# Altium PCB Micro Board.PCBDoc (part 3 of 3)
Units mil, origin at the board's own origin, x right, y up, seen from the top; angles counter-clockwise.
Board outline 8525 x 5525 mil, 2 copper layers (Top Layer, Bottom Layer); 82 components, 533 nets, 1257 pads, 165 vias.
Unrouted connection lines stored in the file: 4.
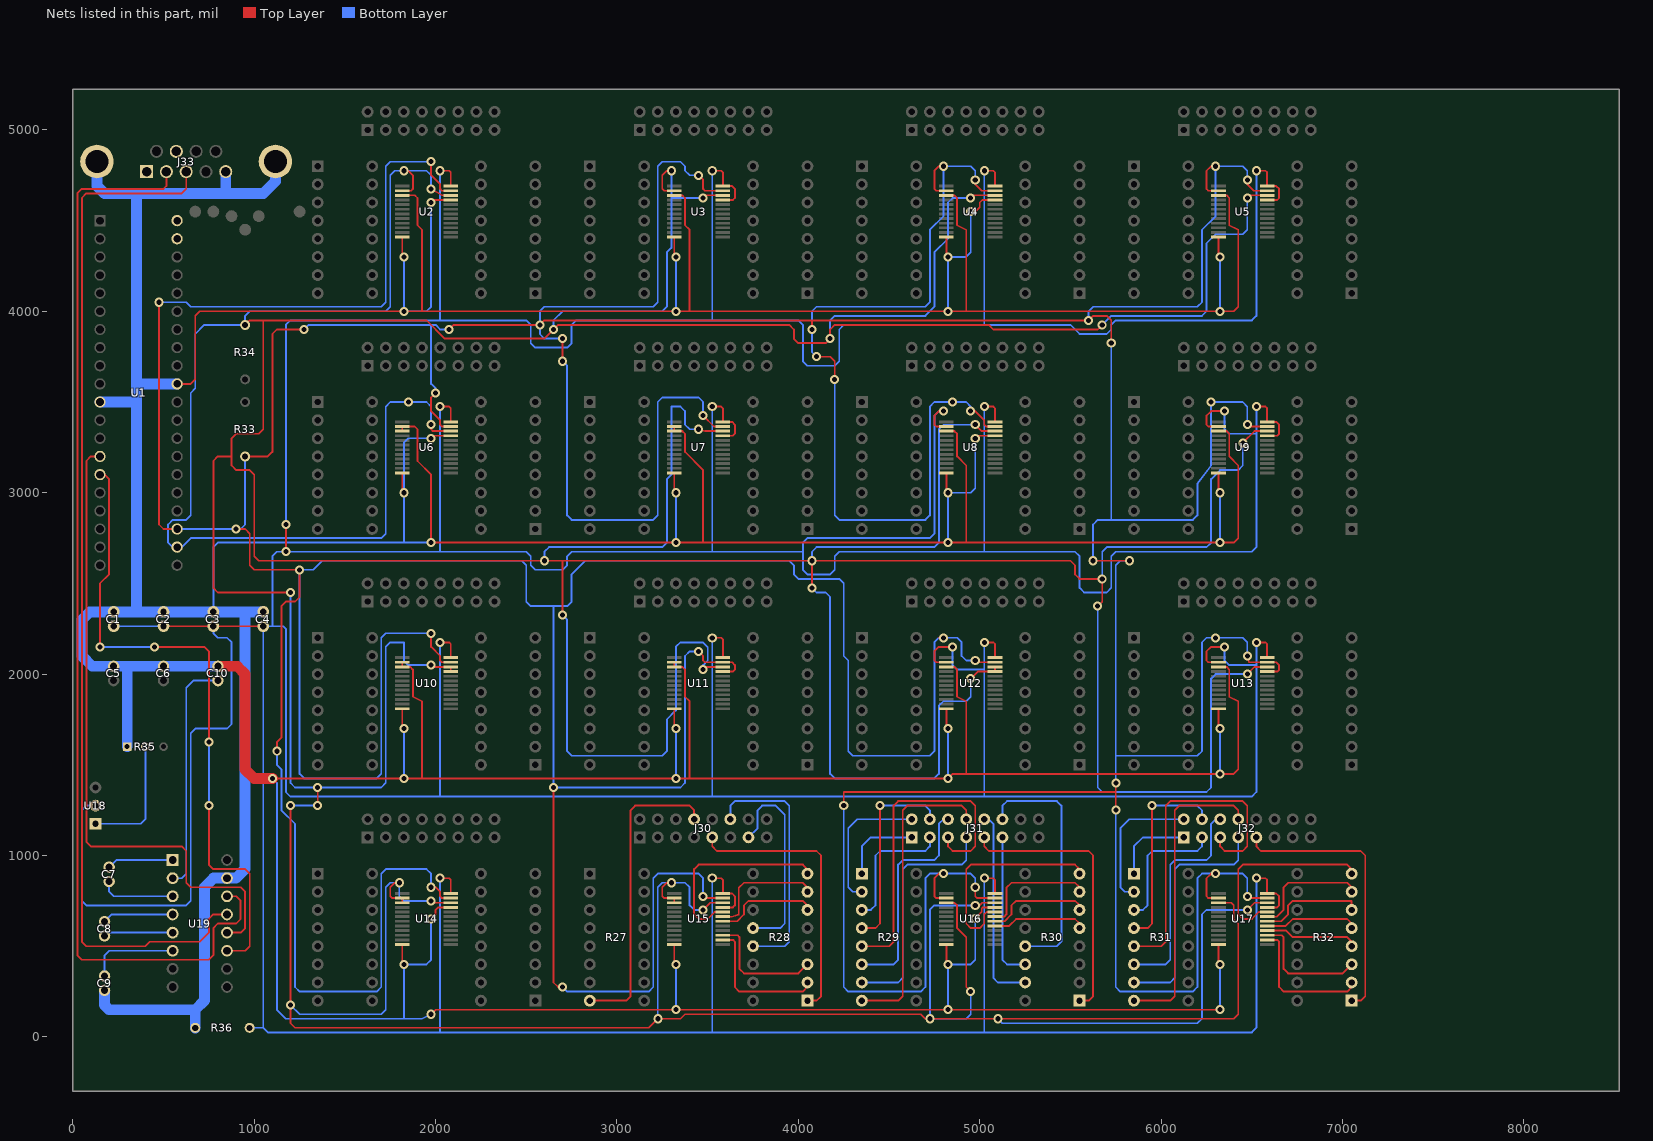
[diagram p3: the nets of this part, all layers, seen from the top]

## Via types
v1: diameter 50, hole 28, Top Layer to Bottom Layer, 165 vias

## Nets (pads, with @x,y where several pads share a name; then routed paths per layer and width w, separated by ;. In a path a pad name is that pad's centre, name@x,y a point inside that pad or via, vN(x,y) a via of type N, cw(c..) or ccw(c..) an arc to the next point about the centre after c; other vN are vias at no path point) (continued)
B216: J30.8 R27.8 | length 1681.1
  Top Layer w10: R27.8@2850,200 3050,200 3075,225 3075,1250 3100,1275 3400,1275 3425,1250 J30.8@3425,1200
B217: R28.16 U15.13 | length 465.9
  Top Layer w10: U15.13@3583.86,509.25 3583.86,216.14 3600,200 R28.16@3750,200
B217: J30.9 R28.1 | length 1531.1
  Top Layer w10: J30.9@3525,1100 3525,1050 3550,1025 4100,1025 4125,1000 4125,225 4100,200 R28.1@4050,200
B218: J30.10 R28.15 | length 1095.7
  Bottom Layer w10: J30.10@3525,1200 3550,1200 3575,1175 3575,325 3600,300 R28.15@3750,300
B218: R28.2 U15.14 | length 765.9
  Top Layer w10: U15.14@3583.86,534.84 3640.16,534.84 3650,525 3650,275 3675,250 4025,250 4050,275 R28.2@4050,300
B219: J30.11 R28.14 | length 810.4
  Bottom Layer w10: J30.11@3625,1100 3625,425 3650,400 R28.14@3750,400
B219: R28.3 U15.15 | length 676.5
  Top Layer w10: U15.15@3583.86,560.43 3664.57,560.43 3675,550 3675,375 3700,350 4000,350 R28.3@4050,400
B220: R28.4 U15.16 | length 516.4
  Top Layer w10: U15.16@3583.86,586.02 3688.98,586.02 3725,550 4025,550 4050,525 R28.4@4050,500
B220: J30.12 R28.13 | length 1381.1
  Bottom Layer w10: J30.12@3625,1200 3625,1275 3650,1300 3925,1300 3950,1275 3950,525 3925,500 R28.13@3750,500
B221: R28.5 U15.17 | length 517.4
  Top Layer w10: U15.17@3583.86,611.61 3686.61,611.61 3725,650 4025,650 4050,625 R28.5@4050,600
B221: J30.13 R28.12 | length 1137.1
  Bottom Layer w10: J30.13@3725,1100 3775,1150 3775,1250 3800,1275 3875,1275 3925,1225 3925,625 3900,600 R28.12@3750,600
B222: J30.14 R28.11 | length 581.1
  Bottom Layer w10: J30.14@3725,1200 3675,1150 3675,725 3700,700 R28.11@3750,700
B222: R28.6 U15.18 | length 577.5
  Top Layer w10: U15.18@3583.86,637.2 3662.2,637.2 3700,675 3700,725 3725,750 4025,750 4050,725 R28.6@4050,700
B223: J30.15 R28.10 | length 431.1
  Bottom Layer w10: R28.10@3750,800 3725,800 3700,825 3700,950 3725,975 3800,975 3825,1000 J30.15@3825,1100
B223: R28.7 U15.19 | length 661.9
  Top Layer w10: U15.19@3583.86,662.8 3634.51,662.8 3671.72,675 3671.72,821.72 3700,850 4025,850 4050,825 R28.7@4050,800
B224: J30.16 R28.9 | length 495.7
  Bottom Layer w10: R28.9@3750,900 3875,900 3900,925 3900,1175 3875,1200 J30.16@3825,1200
B224: R28.8 U15.20 | length 1105.8
  Top Layer w10: U15.20@3583.86,688.39 3538.39,688.39 3500,650 3450,650 3425,675 3425,925 3450,950 4025,950 4050,925 R28.8@4050,900
B225: R29.16 U16.4 | length 331.1
  Top Layer w10: R29.16@4650,900 4700,900 4725,875 4725,725 4736.02,713.98 U16.4@4816.14,713.98
B225: J31.1 R29.1 | length 445.7
  Bottom Layer w10: R29.1@4350,900 4350,1050 4400,1100 J31.1@4625,1100
B226: R29.15 U16.5 | length 256.3
  Top Layer w10: R29.15@4650,800 4675,800 4700,775 4700,700 4711.61,688.39 U16.5@4816.14,688.39
B226: J31.2 R29.2 | length 781.1
  Bottom Layer w10: R29.2@4350,800 4300,800 4275,825 4275,1150 4325,1200 J31.2@4625,1200
B227: R29.14 U16.6 | length 181.6
  Top Layer w10: R29.14@4650,700 4687.2,662.8 U16.6@4816.14,662.8
B227: J31.3 R29.3 | length 731.1
  Bottom Layer w10: R29.3@4350,700 4400,700 4425,725 4425,1000 4450,1025 4700,1025 4725,1050 J31.3@4725,1100
B228: R29.13 U16.7 | length 146.2
  Top Layer w10: 4675,625 4687.2,637.2 U16.7@4816.14,637.2
B228: J31.4 R29.4 | length 1095.7
  Top Layer w10: R29.4@4350,600 4425,600 4450,625 v1(4450,1275)
  Bottom Layer w10: v1(4450,1275) 4700,1275 4725,1250 J31.4@4725,1200
B229: R29.12 U16.8 | length 256.3
  Top Layer w10: R29.12@4650,500 4675,500 4700,525 4700,600 4711.61,611.61 U16.8@4816.14,611.61
B229: J31.5 R29.5 | length 1851.8
  Top Layer w10: R29.5@4350,500 4500,500 4525,525 4525,1275 4550,1300 4950,1300 4975,1275 4975,1050 4950,1025 4850,1025 4825,1050 J31.5@4825,1100
B230: R29.11 U16.9 | length 331.1
  Top Layer w10: R29.11@4650,400 4700,400 4725,425 4725,575 4736.02,586.02 U16.9@4816.14,586.02
B230: J31.6 R29.6 | length 1216.4
  Bottom Layer w10: R29.6@4350,400 4525,400 4550,425 4550,950 4575,975 4750,975 4775,1000 4775,1175 4800,1200 J31.6@4825,1200
B231: R29.10 U16.10 | length 405.8
  Top Layer w10: R29.10@4650,300 4725,300 4750,325 4750,550 4760.43,560.43 U16.10@4816.14,560.43
B231: J31.7 R29.7 | length 1331.1
  Bottom Layer w10: R29.7@4350,300 4550,300 4575,325 4575,925 4600,950 4900,950 4925,975 J31.7@4925,1100
B232: R29.9 U16.11 | length 648.3
  Top Layer w10: R29.9@4650,200 4875,200 4900,225 4900,525 4890.16,534.84 U16.11@4816.14,534.84
B232: J31.8 R29.8 | length 1681.1
  Top Layer w10: R29.8@4350,200 4550,200 4575,225 4575,1250 4600,1275 4900,1275 4925,1250 J31.8@4925,1200
B233: R30.16 U16.13 | length 465.9
  Top Layer w10: U16.13@5083.86,509.25 5083.86,216.14 5100,200 R30.16@5250,200
B233: J31.9 R30.1 | length 1531.1
  Top Layer w10: J31.9@5025,1100 5025,1050 5050,1025 5600,1025 5625,1000 5625,225 5600,200 R30.1@5550,200
B234: R30.2 U16.14 | length 765.9
  Top Layer w10: U16.14@5083.86,534.84 5140.16,534.84 5150,525 5150,275 5175,250 5525,250 5550,275 R30.2@5550,300
B234: J31.10 R30.15 | length 1095.7
  Bottom Layer w10: J31.10@5025,1200 5050,1200 5075,1175 5075,325 5100,300 R30.15@5250,300
B235: R30.3 U16.15 | length 676.5
  Top Layer w10: U16.15@5083.86,560.43 5164.57,560.43 5175,550 5175,375 5200,350 5500,350 R30.3@5550,400
B235: J31.11 R30.14 | length 810.4
  Bottom Layer w10: J31.11@5125,1100 5125,425 5150,400 R30.14@5250,400
B236: R30.4 U16.16 | length 516.4
  Top Layer w10: U16.16@5083.86,586.02 5188.98,586.02 5225,550 5525,550 5550,525 R30.4@5550,500
B236: J31.12 R30.13 | length 1381.1
  Bottom Layer w10: J31.12@5125,1200 5125,1275 5150,1300 5425,1300 5450,1275 5450,525 5425,500 R30.13@5250,500
B237: J31.13 R30.12 | length 1137.1
  Bottom Layer w10: J31.13@5225,1100 5275,1150 5275,1250 5300,1275 5375,1275 5425,1225 5425,625 5400,600 R30.12@5250,600
B237: R30.5 U16.17 | length 517.4
  Top Layer w10: U16.17@5083.86,611.61 5161.61,611.61 5200,650 5525,650 5550,625 R30.5@5550,600
B238: J31.14 R30.11 | length 581.1
  Bottom Layer w10: J31.14@5225,1200 5175,1150 5175,725 5200,700 R30.11@5250,700
B238: R30.6 U16.18 | length 577.5
  Top Layer w10: U16.18@5083.86,637.2 5137.2,637.2 5175,675 5175,725 5200,750 5525,750 5550,725 R30.6@5550,700
B239: J31.15 R30.10 | length 431.1
  Bottom Layer w10: R30.10@5250,800 5225,800 5200,825 5200,950 5225,975 5300,975 5325,1000 J31.15@5325,1100
B239: R30.7 U16.19 | length 665
  Top Layer w10: U16.19@5083.86,662.8 5134.51,662.8 5146.72,675 5146.72,821.72 5175,850 5525,850 5550,825 R30.7@5550,800
B240: J31.16 R30.9 | length 495.7
  Bottom Layer w10: R30.9@5250,900 5375,900 5400,925 5400,1175 5375,1200 J31.16@5325,1200
B240: R30.8 U16.20 | length 1205.8
  Top Layer w10: U16.20@5083.86,688.39 5038.39,688.39 5025,675 5025,625 5000,600 4950,600 4925,625 4925,925 4950,950 5525,950 5550,925 R30.8@5550,900
B241: R31.16 U17.4 | length 331.1
  Top Layer w10: R31.16@6150,900 6200,900 6225,875 6225,725 6236.02,713.98 U17.4@6316.14,713.98
B241: J32.1 R31.1 | length 445.7
  Bottom Layer w10: R31.1@5850,900 5850,1050 5900,1100 J32.1@6125,1100
B242: R31.15 U17.5 | length 256.3
  Top Layer w10: R31.15@6150,800 6175,800 6200,775 6200,700 6211.61,688.39 U17.5@6316.14,688.39
B242: J32.2 R31.2 | length 781.1
  Bottom Layer w10: R31.2@5850,800 5800,800 5775,825 5775,1150 5825,1200 J32.2@6125,1200
B243: R31.14 U17.6 | length 181.6
  Top Layer w10: R31.14@6150,700 6187.2,662.8 U17.6@6316.14,662.8
B243: J32.3 R31.3 | length 731.1
  Bottom Layer w10: R31.3@5850,700 5900,700 5925,725 5925,1000 5950,1025 6200,1025 6225,1050 J32.3@6225,1100
B244: R31.13 U17.7 | length 146.2
  Top Layer w10: 6175,625 6187.2,637.2 U17.7@6316.14,637.2
B244: J32.4 R31.4 | length 1095.7
  Top Layer w10: R31.4@5850,600 5925,600 5950,625 v1(5950,1275)
  Bottom Layer w10: v1(5950,1275) 6200,1275 6225,1250 J32.4@6225,1200
B245: R31.12 U17.8 | length 256.3
  Top Layer w10: R31.12@6150,500 6175,500 6200,525 6200,600 6211.61,611.61 U17.8@6316.14,611.61
B245: J32.5 R31.5 | length 1851.8
  Top Layer w10: R31.5@5850,500 6000,500 6025,525 6025,1275 6050,1300 6450,1300 6475,1275 6475,1050 6450,1025 6350,1025 6325,1050 J32.5@6325,1100
B246: R31.11 U17.9 | length 331.1
  Top Layer w10: R31.11@6150,400 6200,400 6225,425 6225,575 6236.02,586.02 U17.9@6316.14,586.02
B246: J32.6 R31.6 | length 1216.4
  Bottom Layer w10: R31.6@5850,400 6025,400 6050,425 6050,950 6075,975 6250,975 6275,1000 6275,1175 6300,1200 J32.6@6325,1200
B247: R31.10 U17.10 | length 405.8
  Top Layer w10: R31.10@6150,300 6225,300 6250,325 6250,550 6260.43,560.43 U17.10@6316.14,560.43
B247: J32.7 R31.7 | length 1331.1
  Bottom Layer w10: R31.7@5850,300 6050,300 6075,325 6075,925 6100,950 6400,950 6425,975 J32.7@6425,1100
B248: R31.9 U17.11 | length 648.3
  Top Layer w10: R31.9@6150,200 6375,200 6400,225 6400,525 6390.16,534.84 U17.11@6316.14,534.84
B248: J32.8 R31.8 | length 1681.1
  Top Layer w10: R31.8@5850,200 6050,200 6075,225 6075,1250 6100,1275 6400,1275 6425,1250 J32.8@6425,1200
B249: R32.16 U17.13 | length 465.9
  Top Layer w10: U17.13@6583.86,509.25 6583.86,216.14 6600,200 R32.16@6750,200
B249: J32.9 R32.1 | length 1531.1
  Top Layer w10: J32.9@6525,1100 6525,1050 6550,1025 7100,1025 7125,1000 7125,225 7100,200 R32.1@7050,200
B250: J32.10 R32.15 | length 1095.7
  Bottom Layer w10: J32.10@6525,1200 6550,1200 6575,1175 6575,325 6600,300 R32.15@6750,300
B250: R32.2 U17.14 | length 765.9
  Top Layer w10: U17.14@6583.86,534.84 6640.16,534.84 6650,525 6650,275 6675,250 7025,250 7050,275 R32.2@7050,300
B251: J32.11 R32.14 | length 810.4
  Bottom Layer w10: J32.11@6625,1100 6625,425 6650,400 R32.14@6750,400
B251: R32.3 U17.15 | length 676.5
  Top Layer w10: U17.15@6583.86,560.43 6664.57,560.43 6675,550 6675,375 6700,350 7000,350 R32.3@7050,400
B252: J32.12 R32.13 | length 1381.1
  Bottom Layer w10: J32.12@6625,1200 6625,1275 6650,1300 6925,1300 6950,1275 6950,525 6925,500 R32.13@6750,500
B252: R32.4 U17.16 | length 516.4
  Top Layer w10: U17.16@6583.86,586.02 6688.98,586.02 6725,550 7025,550 7050,525 R32.4@7050,500
B253: J32.13 R32.12 | length 1137.1
  Bottom Layer w10: J32.13@6725,1100 6775,1150 6775,1250 6800,1275 6875,1275 6925,1225 6925,625 6900,600 R32.12@6750,600
B253: R32.5 U17.17 | length 517.4
  Top Layer w10: U17.17@6583.86,611.61 6686.61,611.61 6725,650 7025,650 7050,625 R32.5@7050,600
B254: J32.14 R32.11 | length 581.1
  Bottom Layer w10: J32.14@6725,1200 6675,1150 6675,725 6700,700 R32.11@6750,700
B254: R32.6 U17.18 | length 592.2
  Top Layer w10: U17.18@6583.86,637.2 6662.2,637.2 6700,675 6700,725 6725,750 7050,750 7050,725 R32.6@7050,700
B255: J32.15 R32.10 | length 431.1
  Bottom Layer w10: R32.10@6750,800 6725,800 6700,825 6700,950 6725,975 6800,975 6825,1000 J32.15@6825,1100
B255: R32.7 U17.19 | length 652.3
  Top Layer w10: U17.19@6583.86,662.8 6637.8,662.8 6675,700 6675,825 6700,850 7025,850 7050,825 R32.7@7050,800
B256: J32.16 R32.9 | length 495.7
  Bottom Layer w10: R32.9@6750,900 6875,900 6900,925 6900,1175 6875,1200 J32.16@6825,1200
B256: R32.8 U17.20 | length 1105.8
  Top Layer w10: U17.20@6583.86,688.39 6538.39,688.39 6500,650 6450,650 6425,675 6425,925 6450,950 7025,950 7050,925 R32.8@7050,900
GND: C1.2 C2.2 C3.2 C4.2 C5.2 C6.2 C9.2 C10.2 J33.5 J33.10 J33.11 R35.1 R36.1 U1.11 U1.31 U2.3 U2.12 U2.21 U3.3 U3.12 U4.3 U4.12 U4.21 U5.3 U5.12 U6.2 U6.3 U6.12 U6.21 U7.2 U7.3 U7.12 U8.3 U8.12 U8.21 U9.3 U9.12 U10.2 U10.3 U10.12 U11.2 U11.3 U11.12 U12.3 U12.12 U13.3 U13.12 U14.12 U14.21 U15.12 U16.12 U16.21 U17.12 U19.15 | length 52850.7
  Top Layer w10: U1.31@575,3600 650,3600 675,3625 675,3975 700,4000 6400,4000 6425,4025 6425,4450 6375,4475 6375,4625 6360.43,4639.57 U5.3@6316.14,4639.57 ; v1(1100,1425) v1(4825,1425) 4850,1450 6400,1450 6425,1475 6425,1850 6375,1875 6375,2025 6360.43,2039.57 U13.3@6316.14,2039.57 ; U14.12@1816.14,509.25 1816.14,408.86 v1(1825,400) ; U10.12@1816.14,1809.25 1816.14,1708.86 v1(1825,1700) ; U10.2@1816.14,2065.16 U10.3@1816.14,2039.57 1860.43,2039.57 1875,2025 1875,1875 1925,1850 1925,1425 ; U6.12@1816.14,3109.25 1816.14,3008.86 v1(1825,3000) ; U6.3@1816.14,3339.57 U6.2@1816.14,3365.16 1884.84,3365.16 1900,3350 1900,3175 1975,3100 v1(1975,2725) 6400,2725 6425,2750 6425,3150 6375,3200 6375,3325 6360.43,3339.57 U9.3@6316.14,3339.57 ; U2.12@1816.14,4409.25 1816.14,4308.86 v1(1825,4300) ; U2.3@1816.14,4639.57 1885.43,4639.57 1900,4625 1900,4475 1925,4450 1925,4000 ; v1(1975,125) 2000,150 v1(6325,150) ; v1(1975,650) 2000,675 2000,700 2013.98,713.98 U14.21@2083.86,713.98 ; v1(1975,3300) 1988.98,3313.98 U6.21@2083.86,3313.98 ; v1(1975,4600) 1988.98,4613.98 U2.21@2083.86,4613.98 ; U15.12@3316.14,509.25 3316.14,408.86 v1(3325,400) ; U11.12@3316.14,1809.25 3316.14,1708.86 v1(3325,1700) ; U11.2@3316.14,2065.16 U11.3@3316.14,2039.57 3360.43,2039.57 3375,2025 3375,1875 3400,1850 3400,1425 ; U7.12@3316.14,3109.25 3316.14,3008.86 v1(3325,3000) ; U7.2@3316.14,3365.16 U7.3@3316.14,3339.57 3360.43,3339.57 3375,3325 3375,3225 3475,3125 3475,2725 ; U3.12@3316.14,4409.25 3316.14,4308.86 v1(3325,4300) ; U3.3@3316.14,4639.57 3360.43,4639.57 3375,4625 3375,4475 3400,4450 3400,4000 ; U16.12@4816.14,509.25 4816.14,408.86 v1(4825,400) ; U12.12@4816.14,1809.25 4816.14,1708.86 v1(4825,1700) ; U12.3@4816.14,2039.57 4860.43,2039.57 4875,2025 4875,1875 4925,1850 4925,1450 ; U8.12@4816.14,3109.25 4816.14,3008.86 v1(4825,3000) ; U8.3@4816.14,3339.57 4860.43,3339.57 4875,3325 4875,3200 4925,3150 4925,2725 ; U4.12@4816.14,4409.25 4816.14,4308.86 v1(4825,4300) ; U4.3@4816.14,4639.57 4860.43,4639.57 4875,4625 4875,4475 4925,4450 4925,4000 ; v1(4950,4550) 4975,4550 5000,4575 5000,4600 5013.98,4613.98 U4.21@5083.86,4613.98 ; v1(4975,653.06) 5011.01,689.07 5011.01,707.95 5017.04,713.98 U16.21@5083.86,713.98 ; v1(4975,3300) 4988.98,3313.98 U8.21@5083.86,3313.98 ; U17.12@6316.14,509.25 6316.14,408.86 v1(6325,400) ; U13.12@6316.14,1809.25 6316.14,1708.86 v1(6325,1700) ; U9.12@6316.14,3109.25 6316.14,3008.86 v1(6325,3000) ; U5.12@6316.14,4409.25 6316.14,4308.86 v1(6325,4300)
  Top Layer w60: C10.2@800,2043.11 906.89,2043.11 950,2000 950,1475 1000,1425 v1(1100,1425)
  Bottom Layer w10: C5.2@218.11,2050 C5.2@225,2043.11 ; C3.2@775,2343.11 775,2700 800,2725 v1(1975,2725) ; v1(1100,1425) 1125,1400 1125,150 1175,100 1925,100 v1(1975,125) ; 1825,100 v1(1825,400) 1950,400 1975,425 v1(1975,650) ; v1(1825,1425) v1(1825,1700) ; 1825,2725 1825,3275 1850,3300 v1(1975,3300) ; v1(1825,4300) v1(1825,4000) 1950,4000 1975,4025 v1(1975,4600) ; v1(3325,150) v1(3325,400) ; v1(3325,1425) v1(3325,1700) ; v1(3325,2725) v1(3325,3000) ; v1(3325,4000) v1(3325,4300) ; v1(4825,150) v1(4825,400) 4950,400 4975,425 v1(4975,653.06) ; v1(4825,1425) v1(4825,1700) ; v1(4825,2725) v1(4825,3000) 4950,3000 4975,3025 v1(4975,3300) ; v1(4825,4000) v1(4825,4300) 4925,4300 4950,4325 v1(4950,4550) ; v1(6325,150) v1(6325,400) ; v1(6325,1450) v1(6325,1700) ; v1(6325,2725) v1(6325,3000) ; v1(6325,4000) v1(6325,4300)
  Bottom Layer w60: J33.10@133.07,4825.98 133.07,4691.93 175,4650 1050,4650 1116.93,4716.93 J33.11@1116.93,4825.98 ; U1.11@150,3500 350,3500 ; C9.2@175,256.89 175,175 200,150 675,150 ; R35.1@300,1600 300,2043.11 ; 350,2343.11 350,4650 ; 350,3600 U1.31@575,3600 ; R36.1@675,50 675,150 ; C10.2@800,2043.11 106.89,2043.11 50,2100 50,2300 93.11,2343.11 C4.2@1050,2343.11 ; J33.5@843.11,4770.08 843.11,4656.89 850,4650 ; 950,2343.11 950,925 900,875 775,875 725,825 725,200 675,150
NetC1_1: C1.1 C2.1 C3.1 C4.1 R36.2 U2.24 U3.21 U3.24 U4.24 U5.21 U5.24 U6.24 U7.21 U7.24 U8.2 U8.24 U9.2 U9.21 U9.24 U10.24 U11.24 U12.2 U12.24 U13.2 U13.24 U14.24 U15.21 U15.24 U16.24 U17.21 U17.24 U18.2 | length 51765.2
  Top Layer w10: C2.1@500,2264.37 C4.1@1050,2264.37 ; v1(1175,2675) v1(1175,2825) ; v1(2025,875) 2075,875 2083.86,866.14 U14.24@2083.86,790.75 ; v1(2025,2175) 2075,2175 2083.86,2166.14 U10.24@2083.86,2090.75 ; v1(2025,3475) 2075,3475 2083.86,3466.14 U6.24@2083.86,3390.75 ; v1(2025,4775) 2075,4775 2083.86,4766.14 U2.24@2083.86,4690.75 ; v1(3525,875) 3575,875 3583.86,866.14 U15.24@3583.86,790.75 3634.25,790.75 3650,775 3650,725 3638.98,713.98 U15.21@3583.86,713.98 ; v1(3525,2200) 3575,2200 3583.86,2191.14 U11.24@3583.86,2090.75 ; v1(3525,3475) 3575,3475 3583.86,3466.14 U7.24@3583.86,3390.75 3634.25,3390.75 3650,3375 3650,3325 3638.98,3313.98 U7.21@3583.86,3313.98 ; v1(3525,4775) 3575,4775 3583.86,4766.14 U3.24@3583.86,4690.75 3634.25,4690.75 3650,4675 3650,4625 3638.98,4613.98 U3.21@3583.86,4613.98 ; v1(4800,3450) 4775,3450 4750,3425 4750,3375 4759.84,3365.16 U8.2@4816.14,3365.16 ; U12.2@4816.14,2065.16 4759.84,2065.16 4750,2075 4750,2125 4775,2150 v1(4850,2150) ; v1(5025,875) 5075,875 5083.86,866.14 U16.24@5083.86,790.75 ; v1(5025,2175) 5075,2175 5083.86,2166.14 U12.24@5083.86,2090.75 ; v1(5025,3475) 5075,3475 5083.86,3466.14 U8.24@5083.86,3390.75 ; v1(5025,4775) 5075,4775 5083.86,4766.14 U4.24@5083.86,4690.75 ; U13.2@6316.14,2065.16 6259.84,2065.16 6250,2075 6250,2125 6275,2150 v1(6350,2150) ; U9.2@6316.14,3365.16 6259.84,3365.16 6250,3375 6250,3425 6275,3450 v1(6350,3450) ; v1(6525,875) 6575,875 6583.86,866.14 U17.24@6583.86,790.75 6634.25,790.75 6650,775 6650,725 6638.98,713.98 U17.21@6583.86,713.98 ; v1(6525,2175) 6575,2175 6583.86,2166.14 U13.24@6583.86,2090.75 ; v1(6525,3475) 6575,3475 6583.86,3466.14 U9.24@6583.86,3390.75 6634.25,3390.75 6650,3375 6650,3325 6638.98,3313.98 U9.21@6583.86,3313.98 ; v1(6525,4775) 6575,4775 6583.86,4766.14 U5.24@6583.86,4690.75 6634.25,4690.75 6650,4675 6650,4625 6638.98,4613.98 U5.21@6583.86,4613.98
  Bottom Layer w10: U18.2@125,1275 75,1275 50,1250 50,750 75,725 625,725 650,750 650,1675 675,1700 850,1700 875,1725 875,2175 850,2200 800,2200 775,2225 C3.1@775,2264.37 ; C1.1@225,2264.37 C2.1@500,2264.37 ; R36.2@975,50 1050,50 ; 1100,2264.37 1100,2650 1125,2675 2500,2675 2525,2650 2525,2600 2550,2575 2700,2575 2725,2600 2725,2650 2750,2675 4025,2675 ; v1(1175,2825) 1175,3925 1200,3950 2500,3950 2525,3925 2525,3825 2550,3800 2725,3800 2750,3825 2750,3925 2775,3950 4000,3950 4025,3925 4025,3725 4050,3700 4200,3700 4225,3725 4225,3900 4250,3925 5500,3925 5550,3875 5700,3875 5725,3900 5725,3925 5750,3950 6500,3950 6525,3975 v1(6525,4775) ; 2025,25 v1(2025,875) ; 2025,1325 v1(2025,2175) ; 2025,2675 v1(2025,3475) ; 2025,3950 v1(2025,4775) ; 3525,25 v1(3525,875) ; 3525,1325 v1(3525,2200) ; 3525,2675 v1(3525,3475) ; 3525,3950 v1(3525,4775) ; v1(4800,3450) 4775,3450 4750,3425 4750,2775 4725,2750 4050,2750 4025,2725 4025,2575 4050,2550 4175,2550 4200,2575 4200,2650 4225,2675 5525,2675 5550,2650 5550,2475 5575,2450 5700,2450 5725,2475 5725,2650 5750,2675 6500,2675 6525,2700 v1(6525,3475) ; v1(4850,2150) 4850,2050 4875,2025 5025,2025 ; 5025,25 v1(5025,875) ; 5025,1325 v1(5025,2175) ; 5025,2675 v1(5025,3475) ; 5025,3925 v1(5025,4775) ; v1(6350,2150) 6350,2075 6375,2050 6525,2050 ; v1(6350,3450) 6350,3350 6375,3325 6525,3325 ; v1(6525,875) 6525,50 6500,25 1075,25 1050,50 ; v1(6525,2175) 6525,1350 6500,1325 1200,1325 1175,1350 1175,2250 1160.63,2264.37 C4.1@1050,2264.37 1050,50
NetC7_1: C7.1 U19.1 | length 366.3
  Bottom Layer w10: C7.1@200,935.63 239.37,975 U19.1@550,975
NetC7_2: C7.2 U19.3 | length 417.2
  Bottom Layer w10: C7.2@200,856.89 200,800 225,775 U19.3@550,775
NetC8_1: C8.1 U19.4 | length 391.3
  Bottom Layer w10: C8.1@175,635.63 214.37,675 U19.4@550,675
NetC8_2: C8.2 U19.5 | length 382.5
  Bottom Layer w10: C8.2@175,556.89 193.11,575 U19.5@550,575
NetC9_1: C9.1 U19.6 | length 499.7
  Bottom Layer w10: C9.1@175,335.63 175,450 200,475 U19.6@550,475
NetC10_1: C10.1 U19.2 | length 1301.7
  Bottom Layer w10: U19.2@550,875 600,875 625,900 625,1925 664.37,1964.37 C10.1@800,1964.37
NetJ33_1: J33.1
NetJ33_2: J33.2 U19.14 | length 6063.8
  Top Layer w10: J33.2@515.94,4770.08 515.94,4690.94 500,4675 50,4675 25,4650 25,450 50,425 750,425 775,450 775,600 800,625 900,625 925,650 925,750 900,775 U19.14@850,775
NetJ33_3: J33.3 U19.13 | length 5717.6
  Top Layer w10: J33.3@625,4770.08 625,4675 600,4650 75,4650 50,4625 50,525 75,500 400,500 425,525 700,525 750,575 750,650 775,675 U19.13@850,675
NetJ33_7: J33.7
NetR2_3: 
NetR33_1: R33.1 U1.23 U2.23 U3.23 U4.2 U4.23 U5.2 U5.23 U6.23 U7.23 U8.23 U9.23 U10.23 U11.21 U11.23 U12.23 U13.21 U13.23 U14.23 U15.23 U16.2 U16.23 U17.2 U17.23 | length 55193.3
  Top Layer w10: v1(475,4050) 475,2825 500,2800 U1.23@575,2800 ; v1(900,2800) 950,2800 975,2775 975,2600 1000,2575 v1(1250,2575) 1250,2425 1225,2400 1175,2400 1150,2375 1150,1650 1125,1625 v1(1125,1575) ; R33.1@950,3200 975,3200 1075,3200 1100,3225 1100,3875 1125,3900 v1(1275,3900) ; v1(1975,825) 2000,825 2025,800 2025,775 2034.84,765.16 U14.23@2083.86,765.16 ; v1(1975,2225) 1975,2150 2025,2100 2025,2075 2034.84,2065.16 U10.23@2083.86,2065.16 ; v1(1975,4825) 1975,4750 2025,4700 2025,4675 2034.84,4665.16 U2.23@2083.86,4665.16 ; v1(2000,3550) 1975,3525 1975,3450 2025,3400 2025,3375 2034.84,3365.16 U6.23@2083.86,3365.16 ; v1(2075,3900) 2100,3925 v1(2575,3925) 2600,3950 v1(5600,3950) 5625,3975 5700,3975 5725,3950 v1(5725,3825) ; v1(2650,1375) 2650,300 2675,275 v1(2700,275) ; v1(2700,3725) v1(2700,3850) ; v1(3450,2125) 3475,2100 3475,2075 3484.84,2065.16 3634.84,2065.16 3650,2050 3650,2025 3638.98,2013.98 U11.21@3583.86,2013.98 ; v1(3450,4750) 3475,4725 3475,4675 3484.84,4665.16 U3.23@3583.86,4665.16 ; v1(3475,775) 3484.84,765.16 U15.23@3583.86,765.16 ; v1(3475,3425) 3534.84,3365.16 U7.23@3583.86,3365.16 ; v1(4075,3900) 4075,3950 ; v1(4100,3750) 4175,3750 4200,3725 v1(4200,3625) ; v1(4250,1275) 4250,1350 5750,1350 ; v1@4775,2200 v1(4800,2200) ; v1(4800,900) 4775,900 4750,875 4750,775 4759.84,765.16 U16.2@4816.14,765.16 ; v1(4800,4800) 4775,4800 4750,4775 4750,4675 4759.84,4665.16 U4.2@4816.14,4665.16 ; v1(4950,3450) 4975,3450 5025,3400 5025,3375 5034.84,3365.16 U8.23@5083.86,3365.16 ; v1(4975,825) 4975,775 4984.84,765.16 U16.23@5083.86,765.16 ; v1(4975,2075) 4984.84,2065.16 U12.23@5083.86,2065.16 ; v1(4975,4725) 4975,4700 5009.84,4665.16 U4.23@5083.86,4665.16 ; v1(5625,2625) v1(5825,2625) ; v1(5750,1250) v1(5750,1400) ; v1(6300,900) 6275,900 6250,875 6250,775 6259.84,765.16 U17.2@6316.14,765.16 ; v1(6300,4800) 6275,4800 6250,4775 6250,4675 6259.84,4665.16 U5.2@6316.14,4665.16 ; v1(6475,775) 6484.84,765.16 U17.23@6583.86,765.16 ; v1(6475,2100) 6484.84,2065.16 6634.84,2065.16 6650,2050 6650,2025 6638.98,2013.98 U13.21@6583.86,2013.98 ; v1(6475,3375) 6484.84,3365.16 U9.23@6583.86,3365.16 ; v1(6475,4725) 6475,4700 6509.84,4665.16 U5.23@6583.86,4665.16
  Bottom Layer w10: v1(475,4050) 625,4050 650,4025 1700,4025 1725,4050 1725,4800 1750,4825 v1(1975,4825) ; U1.23@575,2800 925,2800 950,2825 R33.1@950,3200 ; v1(1125,1575) 1125,1500 1150,1475 1150,1250 1225,1175 1225,275 1250,250 1675,250 1700,275 1700,900 1725,925 1950,925 1975,900 v1(1975,825) ; v1(1275,3900) 1300,3925 2000,3925 2025,3900 v1(2075,3900) ; v1(1975,2225) 1725,2225 1700,2200 1700,1450 1675,1425 1275,1425 1250,1450 v1(1250,2575) 1325,2575 1375,2625 2475,2625 2500,2600 2500,2400 2525,2375 2725,2375 2750,2400 2750,2550 2825,2625 3950,2625 3975,2600 3975,2550 4000,2525 4225,2525 4250,2500 4250,2100 4275,2075 4275,1575 4300,1550 4725,1550 4750,1575 4750,2175 4775,2200 4875,2200 4900,2175 4900,2100 4925,2075 v1(4975,2075) ; 1975,3925 1975,3600 2000,3575 v1(2000,3550) ; 2650,2375 v1(2650,1375) 3350,1375 3375,1400 3375,2100 3400,2125 v1(3450,2125) ; v1(2700,275) 2725,250 3175,250 3200,275 3200,875 3225,900 3450,900 3475,875 v1(3475,775) ; v1(2700,3725) 2725,3700 2725,2875 2750,2850 3200,2850 3225,2875 3225,3500 3250,3525 3450,3525 3475,3500 v1(3475,3425) ; v1(2700,3850) 2600,3850 2575,3875 2575,4000 2600,4025 3200,4025 3225,4050 3225,4800 3250,4825 3350,4825 3375,4800 3375,4775 3400,4750 v1(3450,4750) ; v1(4100,3750) 4075,3775 4075,4000 4100,4025 4700,4025 4725,4050 4725,4450 4800,4525 v1(4800,4800) 4950,4800 4975,4775 v1(4975,4725) ; v1(4200,3625) 4200,2875 4225,2850 4700,2850 4725,2875 4725,3475 4750,3500 4925,3500 4950,3475 v1(4950,3450) ; v1(4250,1275) 4250,275 4275,250 4675,250 4700,275 4700,875 4725,900 4950,900 4975,875 v1(4975,825) ; v1(5600,3950) 5600,4000 5625,4025 6200,4025 6225,4050 6225,4450 6300,4525 v1(6300,4800) 6450,4800 6475,4775 v1(6475,4725) ; v1(5625,2625) 5625,2825 5650,2850 6175,2850 6200,2875 6200,3050 6275,3150 v1(6275,3500) 6450,3500 6475,3475 v1(6475,3375) ; 5725,2850 v1(5725,3825) ; v1(5750,1250) 5750,275 5775,250 6175,250 6200,275 6200,875 6225,900 6450,900 6475,875 v1(6475,775) ; v1(5750,1400) 5750,2600 5775,2625 v1(5825,2625) ; 5750,1550 6200,1550 6225,1575 6225,2175 6250,2200 6450,2200 6475,2175 v1(6475,2100)
  other v1: 6300,2200 4850,3500
NetR34_1: R34.1 U1.22 U2.2 U2.22 U3.2 U3.22 U4.22 U5.22 U6.22 U7.22 U8.22 U9.22 U10.21 U10.22 U11.22 U12.21 U12.22 U13.22 U14.2 U14.3 U14.22 U15.2 U15.3 U15.22 U16.3 U16.22 U17.3 U17.22 | length 54819
  Top Layer w10: 875,3200 800,3200 775,3175 775,2475 800,2450 v1(1200,2450) ; R34.1@950,3925 975,3950 1950,3950 2050,3850 2600,3850 2675,3925 3950,3925 3975,3900 3975,3850 4000,3825 4150,3825 v1(4175,3850) 4175,3900 4200,3925 5050,3925 5075,3900 5650,3900 v1(5675,3925) ; 1050,3950 1050,3350 1025,3325 900,3325 875,3300 875,3150 900,3125 975,3125 1000,3100 1000,2650 1025,2625 5500,2625 5525,2600 5525,2550 5550,2525 v1(5675,2525) 5675,2400 v1(5650,2375) ; v1(1200,1275) 1200,75 1225,50 3175,50 v1(3225,100) 3350,100 3375,125 4675,125 4700,100 6400,100 6425,125 6425,625 6400,650 6400,725 6385.43,739.57 U17.3@6316.14,739.57 ; v1(1350,1275) v1(1350,1375) ; v1(1800,850) 1775,850 1750,825 1750,775 1759.84,765.16 U14.2@1816.14,765.16 U14.3@1816.14,739.57 ; U2.2@1816.14,4665.16 1865.16,4665.16 1875,4675 1875,4750 1850,4775 v1(1825,4775) ; v1(1975,750) 1985.43,739.57 U14.22@2083.86,739.57 ; v1(1975,2050) 1985.43,2039.57 U10.22@2083.86,2039.57 U10.21@2083.86,2013.98 ; v1(1975,3375) 1975,3350 1985.43,3339.57 U6.22@2083.86,3339.57 ; v1(1975,4675) 2035.43,4639.57 U2.22@2083.86,4639.57 ; v1(2700,2325) 2700,2625 ; v1(3300,850) 3275,850 3250,825 3250,775 3259.84,765.16 U15.2@3316.14,765.16 U15.3@3316.14,739.57 ; v1(3300,4775) 3275,4775 3250,4750 3250,4675 3259.84,4665.16 U3.2@3316.14,4665.16 ; v1(3450,3350) 3485.43,3339.57 U7.22@3583.86,3339.57 ; v1(3475,700) 3514.57,739.57 U15.22@3583.86,739.57 ; v1(3475,2025) 3489.57,2039.57 U11.22@3583.86,2039.57 ; v1(3475,4625) 3489.57,4639.57 U3.22@3583.86,4639.57 ; v1(4075,2475) v1(4075,2625) ; U16.3@4816.14,739.57 4860.43,739.57 4875,725 4875,600 4925,550 4925,275 v1(4950,250) ; v1(4950,1975) 4988.98,2013.98 U12.21@5083.86,2013.98 U12.22@5083.86,2039.57 ; v1(4950,4625) 4964.57,4639.57 U4.22@5083.86,4639.57 ; v1(4975,725) 5000,725 5014.57,739.57 U16.22@5083.86,739.57 ; v1(4975,3375) 5010.43,3339.57 U8.22@5083.86,3339.57 ; v1(6450,3275) 6514.57,3339.57 U9.22@6583.86,3339.57 ; v1(6475,700) 6514.57,739.57 U17.22@6583.86,739.57 ; v1(6475,2000) 6514.57,2039.57 U13.22@6583.86,2039.57 ; v1(6475,4625) 6489.57,4639.57 U5.22@6583.86,4639.57
  Bottom Layer w10: v1(1200,175) 1250,125 1700,125 1725,150 1725,825 1750,850 v1(1800,850) 1800,775 1825,750 v1(1975,750) ; v1(1200,1275) v1(1350,1275) ; v1(1200,2450) 1200,1400 1225,1375 1700,1375 1725,1400 1725,2150 1750,2175 1825,2175 1825,2075 1850,2050 v1(1975,2050) ; v1(1975,3375) 1975,3475 1950,3500 1750,3500 1725,3475 1725,2775 1700,2750 1075,2750 1000,2750 650,2750 625,2725 600,2700 U1.22@575,2700 550,2700 525,2725 525,2825 550,2850 625,2850 650,2875 650,3550 675,3575 675,3875 725,3925 R34.1@950,3925 950,3975 975,4000 1725,4000 1750,4025 1750,4750 1775,4775 1950,4775 1975,4750 v1(1975,4675) ; v1(2600,2625) 2600,2675 2625,2700 3250,2700 3275,2725 3275,3075 3300,3100 3300,3475 3350,3475 3375,3450 3375,3375 3400,3350 v1(3450,3350) ; v1(2650,3900) 2650,3950 2700,4000 3250,4000 3275,4025 3275,4325 3300,4350 v1(3300,4775) ; v1(2700,2325) 2725,2300 2725,1575 2750,1550 3250,1550 3275,1575 3275,1750 3325,1800 3325,2150 3350,2175 3473.24,2175 3500,2148.24 3500,2075 3475,2050 v1(3475,2025) ; v1(3225,100) 3225,825 3250,850 3375,850 3400,825 3400,725 3425,700 v1(3475,700) ; 3300,4625 v1(3475,4625) ; v1(4075,2475) 4100,2450 4150,2450 4175,2425 4175,1450 4200,1425 4750,1425 4775,1450 4775,1825 4800,1850 4925,1850 4950,1875 v1(4950,1975) ; v1(4075,2625) 4075,2675 4100,2700 4750,2700 4775,2725 4775,3350 4800,3375 v1(4975,3375) ; v1(4175,3850) 4175,3950 4200,3975 4700,3975 4750,4025 4750,4325 4825,4400 4825,4600 4850,4625 v1(4950,4625) ; v1(4950,250) 4950,125 4925,100 v1(4725,100) 4725,700 4750,725 v1(4975,725) ; v1(5100,100) 5125,75 6200,75 6225,100 6225,675 6250,700 v1(6475,700) ; v1(5650,2375) 5650,1375 5675,1350 6250,1350 6275,1375 6275,1975 6300,2000 v1(6475,2000) ; v1(5675,2525) 5675,2675 5700,2700 6250,2700 6275,2725 6275,3075 6325,3125 6425,3125 6450,3150 v1(6450,3275) ; v1(5675,3925) 5725,3975 6225,3975 6250,4000 6250,4375 6300,4425 6450,4425 6475,4450 v1(6475,4625)
  other v1: 1850,3500
NetR35_2: R35.2 U18.1 | length 685.4
  Bottom Layer w10: U18.1@125,1175 375,1175 400,1200 R35.2@400,1600
NetU1_14: U1.14 U19.12 | length 3587.1
  Top Layer w10: U1.14@150,3200 100,3200 75,3175 75,1075 100,1050 600,1050 625,1025 625,850 650,825 925,825 950,800 950,600 925,575 U19.12@850,575
NetU1_15: U1.15 U19.11 | length 3572.5
  Top Layer w10: v1(150,2150) 150,2500 200,2550 200,3075 175,3100 U1.15@150,3100 ; v1(450,2150) 725,2150 750,2125 v1(750,1625) ; v1(750,1275) 750,950 775,925 950,925 975,900 975,500 950,475 U19.11@850,475
  Bottom Layer w10: v1(150,2150) v1(450,2150) ; v1(750,1275) v1(750,1625)
NetU1_39: U1.39
NetU1_40: U1.40
pads on no net: J33.4 J33.6 J33.8 J33.9 R35.3 U1.1 U1.2 U1.3 U1.4 U1.5 U1.6 U1.7 U1.8 U1.9 U1.12 U1.13 U1.16 U1.17 U1.18 U1.19 U1.20 U1.21 U1.24 U1.25 U1.26 U1.27 U1.28 U1.29 U1.30 U1.32 U1.33 U1.34 U1.35 U1.36 U1.37 U1.38 U2.1 U3.1 U4.1 U5.1 U6.1 U7.1 U8.1 U9.1 U10.1 U11.1 U12.1 U13.1 U14.1 U15.1 U16.1 U17.1 U19.7 U19.8 U19.9 U19.10
copper on no net: | length 4251.7
  Top Layer w10: 406.89,4770.08 406.89,4818.35 400,4825.24 400,4950 425,4975 1200,4975 1225,4950 1250,4925 1250,4550 ; 461.42,4881.89 461.42,4930.16 475,4943.74 956.26,4943.74 975,4925 975,4600 1025,4550 1025,4525 ; 570.47,4881.89 570.47,4833.62 579.09,4825 650,4825 675,4800 675,4779.29 683.07,4771.22 683.07,4558.07 675,4550 ; 679.53,4881.89 679.53,4870.47 700,4850 715.76,4850 740.76,4825 900,4825 925,4800 925,4600 875,4550 875,4525 ; 734.06,4770.08 734.06,4721.81 755.87,4700 755.87,4594.13 775,4575 775,4550 ; 788.58,4881.89 836.85,4881.89 843.74,4875 925,4875 950,4850 950,4550 950,4450

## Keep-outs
Keep-Out Layer:
  lines w10: 0,0 7325,0 7325,5225 0,5225 0,0

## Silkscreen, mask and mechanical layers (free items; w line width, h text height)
Mechanical 1:
  lines w10: 0,0 7325,0 7325,5225 0,5225 0,0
